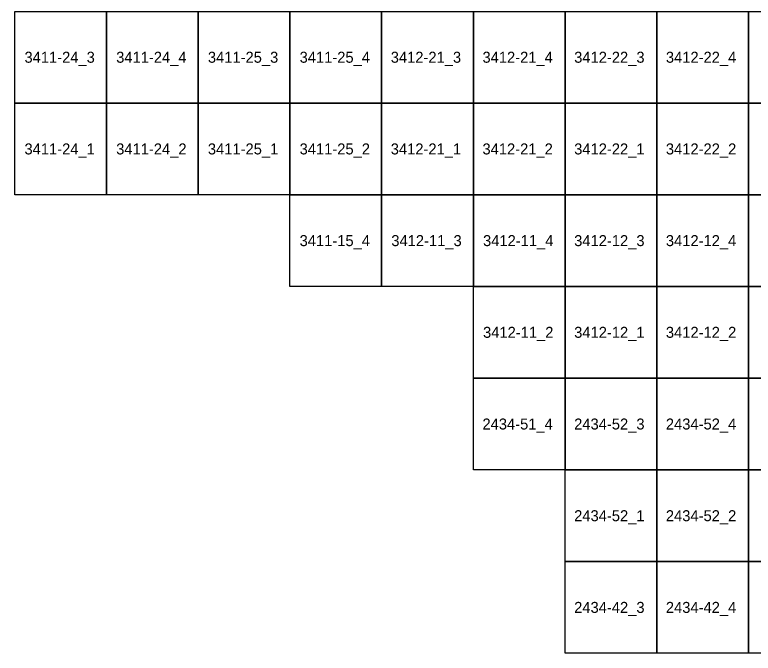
# Model space of a CAD drawing. Extents: x 312500 to 765000, y 172500 to 440000.
# Drawn here: x 615000 to 635129, y 192500 to 209909 of the extents above; entities that cross this region are included whole.
import ezdxf

# ---------------------------------------------------------------- set-up
doc = ezdxf.new("R2010")
doc.units = 0
doc.layers.add('Topo5_ramis_TKS2025', color=7, linetype='Continuous')
doc.layers.add('Topo5_ramis_TKS2025_Nr', color=7, linetype='Continuous')

msp = doc.modelspace()

# ---------------------------------------------------------------- linework, layer by layer
at = {"layer": 'Topo5_ramis_TKS2025'}
for points in [[(615000, 207500), (615000, 210000), (617500, 210000), (617500, 207500), (615000, 207500)], [(617500, 207500), (617500, 210000), (620000, 210000), (620000, 207500), (617500, 207500)], [(620000, 207500), (620000, 210000), (622500, 210000), (622500, 207500), (620000, 207500)], [(622500, 207500), (622500, 210000), (625000, 210000), (625000, 207500), (622500, 207500)], [(625000, 207500), (625000, 210000), (627500, 210000), (627500, 207500), (625000, 207500)], [(627500, 207500), (627500, 210000), (630000, 210000), (630000, 207500), (627500, 207500)], [(630000, 207500), (630000, 210000), (632500, 210000), (632500, 207500), (630000, 207500)], [(632500, 207500), (632500, 210000), (635000, 210000), (635000, 207500), (632500, 207500)], [(635000, 207500), (635000, 210000), (637500, 210000), (637500, 207500), (635000, 207500)], [(615000, 205000), (615000, 207500), (617500, 207500), (617500, 205000), (615000, 205000)], [(617500, 205000), (617500, 207500), (620000, 207500), (620000, 205000), (617500, 205000)], [(620000, 205000), (620000, 207500), (622500, 207500), (622500, 205000), (620000, 205000)], [(622500, 205000), (622500, 207500), (625000, 207500), (625000, 205000), (622500, 205000)], [(625000, 205000), (625000, 207500), (627500, 207500), (627500, 205000), (625000, 205000)], [(627500, 205000), (627500, 207500), (630000, 207500), (630000, 205000), (627500, 205000)], [(630000, 205000), (630000, 207500), (632500, 207500), (632500, 205000), (630000, 205000)], [(632500, 205000), (632500, 207500), (635000, 207500), (635000, 205000), (632500, 205000)], [(635000, 205000), (635000, 207500), (637500, 207500), (637500, 205000), (635000, 205000)], [(622500, 202500), (622500, 205000), (625000, 205000), (625000, 202500), (622500, 202500)], [(625000, 202500), (625000, 205000), (627500, 205000), (627500, 202500), (625000, 202500)], [(627500, 202500), (627500, 205000), (630000, 205000), (630000, 202500), (627500, 202500)], [(630000, 202500), (630000, 205000), (632500, 205000), (632500, 202500), (630000, 202500)], [(632500, 202500), (632500, 205000), (635000, 205000), (635000, 202500), (632500, 202500)], [(635000, 202500), (635000, 205000), (637500, 205000), (637500, 202500), (635000, 202500)], [(627500, 200000), (627500, 202500), (630000, 202500), (630000, 200000), (627500, 200000)], [(630000, 200000), (630000, 202500), (632500, 202500), (632500, 200000), (630000, 200000)], [(632500, 200000), (632500, 202500), (635000, 202500), (635000, 200000), (632500, 200000)], [(635000, 200000), (635000, 202500), (637500, 202500), (637500, 200000), (635000, 200000)], [(627500, 197500), (627500, 200000), (630000, 200000), (630000, 197500), (627500, 197500)], [(630000, 197500), (630000, 200000), (632500, 200000), (632500, 197500), (630000, 197500)], [(632500, 197500), (632500, 200000), (635000, 200000), (635000, 197500), (632500, 197500)], [(635000, 197500), (635000, 200000), (637500, 200000), (637500, 197500), (635000, 197500)], [(630000, 195000), (630000, 197500), (632500, 197500), (632500, 195000), (630000, 195000)], [(632500, 195000), (632500, 197500), (635000, 197500), (635000, 195000), (632500, 195000)], [(635000, 195000), (635000, 197500), (637500, 197500), (637500, 195000), (635000, 195000)], [(630000, 192500), (630000, 195000), (632500, 195000), (632500, 192500), (630000, 192500)], [(632500, 192500), (632500, 195000), (635000, 195000), (635000, 192500), (632500, 192500)], [(635000, 192500), (635000, 195000), (637500, 195000), (637500, 192500), (635000, 192500)]]:
    msp.add_lwpolyline(points, dxfattribs=at)

# ---------------------------------------------------------------- texts
at = {"layer": 'Topo5_ramis_TKS2025_Nr'}
for s, p in [('3411-24_3', (615264, 208600)), ('3411-24_4', (617764, 208600)), ('3411-25_3', (620264, 208600)), ('3411-25_4', (622764, 208600)), ('3412-21_3', (625248, 208600)), ('3412-21_4', (627748, 208600)), ('3412-22_3', (630248, 208600)), ('3412-22_4', (632748, 208600)), ('3411-24_1', (615264, 206100)), ('3411-24_2', (617764, 206100)), ('3411-25_1', (620264, 206100)), ('3411-25_2', (622764, 206100)), ('3412-21_1', (625248, 206100)), ('3412-21_2', (627748, 206100)), ('3412-22_1', (630248, 206100)), ('3412-22_2', (632748, 206100)), ('3411-15_4', (622764, 203600)), ('3412-11_3', (625264, 203600)), ('3412-11_4', (627764, 203600)), ('3412-12_3', (630248, 203600)), ('3412-12_4', (632748, 203600)), ('3412-11_2', (627764, 201100)), ('3412-12_1', (630248, 201100)), ('3412-12_2', (632748, 201100)), ('2434-51_4', (627748, 198600)), ('2434-52_3', (630248, 198600)), ('2434-52_4', (632748, 198600)), ('2434-52_1', (630248, 196100)), ('2434-52_2', (632748, 196100)), ('2434-42_3', (630248, 193600)), ('2434-42_4', (632748, 193600))]:
    msp.add_text(s, height=300, dxfattribs=at).set_placement(p)

doc.saveas('drawing.dxf')
